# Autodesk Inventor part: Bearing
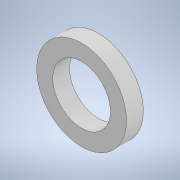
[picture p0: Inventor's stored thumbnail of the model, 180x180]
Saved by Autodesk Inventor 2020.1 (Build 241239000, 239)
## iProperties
Created: 2019-12
Part Number: Bearing
Material: Generic
Document SubType Name: Modeling
Designer: Patrick Everitt
Density: 1 g/cm^3
Appearance: Default
Author: Patrick Everitt
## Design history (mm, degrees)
sketch "Sketch1"
  geometry: C1 r 22.225 at (0, 0); C2 r 14.287 at (0, 0); 1 further point
  constraints: 2 centre point, 2 coincident
  dimensions: "d0" = 44.45 diameter of C1; "d1" = 28.575 diameter of C2
extrude "Extrusion1" new body sketch "Sketch1" distance "d2" = 8.3312; taper "d3" = 0 deg
body "Solid1"
